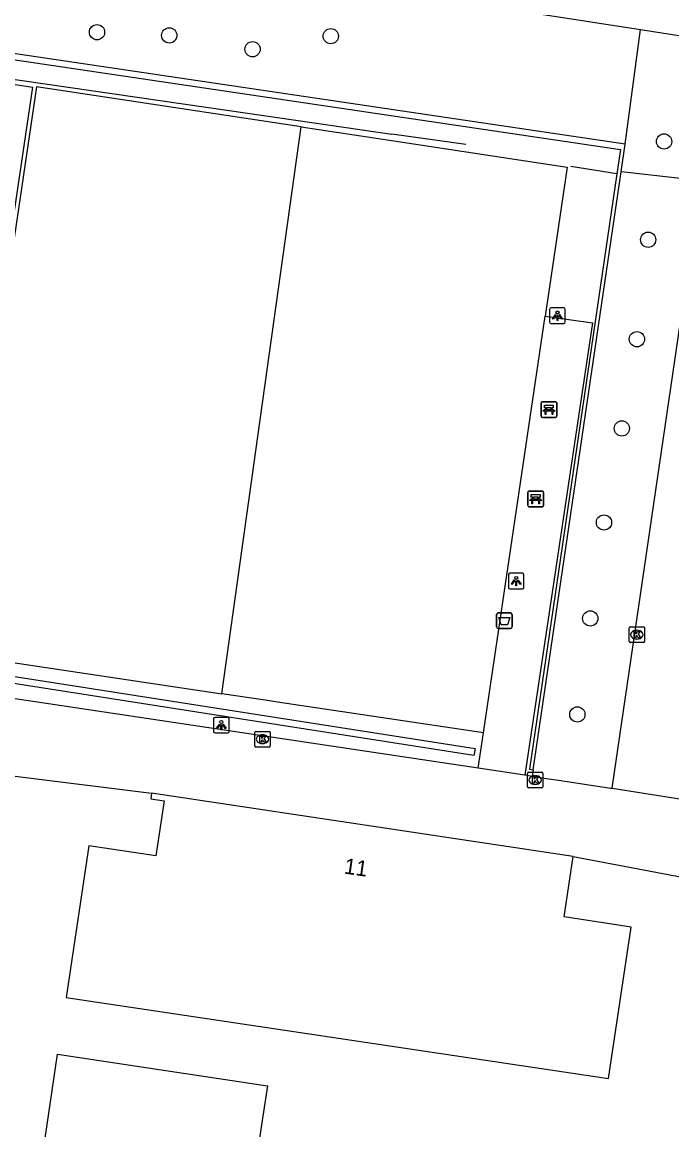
# Model space of a CAD drawing. Extents: x 161094 to 161705, y 379509 to 380907.
# Drawn here: x 161250.2 to 161291.8, y 380398.5 to 380469.4 of the extents above; entities that cross this region are included whole.
import ezdxf

# ---------------------------------------------------------------- set-up
doc = ezdxf.new("R2010")
doc.units = 0
for name, color, linetype in [('IMGEO_Afvalbak', 7, 'Continuous'), ('IMGEO_Bank', 7, 'Continuous'), ('IMGEO_Boom', 7, 'Continuous'), ('IMGEO_Groenvoorziening', 7, 'Continuous'), ('IMGEO_Haag', 7, 'Continuous'), ('IMGEO_Hek', 7, 'Continuous'), ('IMGEO_Kolk', 7, 'Continuous'), ('IMGEO_Lichtpunt', 7, 'Continuous'), ('IMGEO_Pand', 7, 'Continuous'), ('IMGEO_Pand_nummerreeks', 7, 'Continuous'), ('IMGEO_Rijbaan_lokaal_open', 7, 'Continuous'), ('IMGEO_Terreindeel_halfverhard', 7, 'Continuous'), ('IMGEO_Voetpad_gesloten', 7, 'Continuous'), ('IMGEO_Voetpad_open', 7, 'Continuous')]:
    doc.layers.add(name, color=color, linetype=linetype)

msp = doc.modelspace()

# ---------------------------------------------------------------- linework, layer by layer
at = {"layer": 'IMGEO_Afvalbak'}
for p, q in [((161280.569, 380430.712), (161280.569, 380431.512)), ((161280.569, 380431.512), (161280.569, 380430.712)), ((161280.669, 380431.612), (161281.459, 380431.612)), ((161281.459, 380431.612), (161280.669, 380431.612)), ((161281.559, 380431.512), (161281.559, 380430.712)), ((161281.559, 380430.712), (161281.559, 380431.512)), ((161281.459, 380430.612), (161280.669, 380430.612)), ((161280.669, 380430.612), (161281.459, 380430.612))]:
    msp.add_line(p, q, dxfattribs=at)
msp.add_lwpolyline([(161280.712, 380431.326), (161281.416, 380431.326), (161281.267, 380430.856), (161280.861, 380430.856), (161280.712, 380431.326)], dxfattribs=at)
for centre, start, end in [((161280.669, 380431.512), 90, 180), ((161280.669, 380431.512), 90, 180), ((161281.459, 380431.512), 0, 90), ((161281.459, 380431.512), 360, 90), ((161280.669, 380430.712), 180, 270), ((161280.669, 380430.712), 180, 270), ((161281.459, 380430.712), 270, 0), ((161281.459, 380430.712), 270, 0)]:
    msp.add_arc(centre, 0.1, start, end, dxfattribs=at)
at = {"layer": 'IMGEO_Bank'}
for p, q in [((161283.495, 380445.129), (161284.336, 380445.129)), ((161284.336, 380445.129), (161283.495, 380445.129)), ((161283.42, 380444.204), (161283.42, 380445.045)), ((161283.42, 380445.045), (161283.42, 380444.204)), ((161284.117, 380444.527), (161283.724, 380444.527)), ((161283.729, 380444.635), (161283.729, 380444.741)), ((161283.773, 380444.741), (161283.773, 380444.635)), ((161284.061, 380444.747), (161283.779, 380444.747)), ((161283.779, 380444.629), (161284.061, 380444.629)), ((161284.067, 380444.635), (161284.067, 380444.741)), ((161284.111, 380444.741), (161284.111, 380444.635)), ((161284.42, 380445.054), (161284.42, 380444.213)), ((161284.42, 380444.213), (161284.42, 380445.054)), ((161284.345, 380444.129), (161283.504, 380444.129)), ((161283.504, 380444.129), (161284.345, 380444.129)), ((161282.575, 380438.48), (161282.575, 380439.321)), ((161282.575, 380439.321), (161282.575, 380438.48)), ((161282.65, 380439.405), (161283.491, 380439.405)), ((161283.491, 380439.405), (161282.65, 380439.405)), ((161283.272, 380438.803), (161282.879, 380438.803)), ((161282.884, 380438.911), (161282.884, 380439.017)), ((161282.928, 380439.017), (161282.928, 380438.911)), ((161283.216, 380439.023), (161282.934, 380439.023)), ((161282.934, 380438.905), (161283.216, 380438.905)), ((161283.222, 380438.911), (161283.222, 380439.017)), ((161283.266, 380439.017), (161283.266, 380438.911)), ((161283.575, 380439.33), (161283.575, 380438.489)), ((161283.575, 380438.489), (161283.575, 380439.33)), ((161283.5, 380438.405), (161282.659, 380438.405)), ((161282.659, 380438.405), (161283.5, 380438.405))]:
    msp.add_line(p, q, dxfattribs=at)
for points in [[(161283.667, 380444.527), (161283.525, 380444.527), (161283.637, 380444.629), (161283.723, 380444.629)], [(161283.723, 380444.747), (161283.637, 380444.747), (161283.637, 380444.908), (161284.2, 380444.908), (161284.2, 380444.747), (161284.117, 380444.747)], [(161283.717, 380444.52), (161283.717, 380444.313), (161283.674, 380444.313), (161283.674, 380444.52)], [(161284.117, 380444.629), (161284.2, 380444.629), (161284.312, 380444.527), (161284.173, 380444.527)], [(161284.167, 380444.52), (161284.167, 380444.313), (161284.123, 380444.313), (161284.123, 380444.52)], [(161282.822, 380438.803), (161282.68, 380438.803), (161282.792, 380438.905), (161282.878, 380438.905)], [(161282.878, 380439.023), (161282.792, 380439.023), (161282.792, 380439.184), (161283.355, 380439.184), (161283.355, 380439.023), (161283.272, 380439.023)], [(161282.872, 380438.796), (161282.872, 380438.589), (161282.829, 380438.589), (161282.829, 380438.796)], [(161283.272, 380438.905), (161283.355, 380438.905), (161283.467, 380438.803), (161283.328, 380438.803)], [(161283.322, 380438.796), (161283.322, 380438.589), (161283.278, 380438.589), (161283.278, 380438.796)]]:
    msp.add_lwpolyline(points, dxfattribs=at)
for centre, radius, start, end in [((161283.498, 380445.051), 0.0779, 92.4484, 184.28452), ((161283.498, 380445.051), 0.0779, 92.4484, 184.28452), ((161284.342, 380445.051), 0.0779, 2.4484, 94.28452), ((161284.342, 380445.051), 0.0779, 2.4484, 94.28452), ((161283.667, 380444.52), 0.00671, 2.89567, 87.10433), ((161283.724, 380444.52), 0.00671, 92.89567, 177.10433), ((161283.722, 380444.74), 0.00671, 2.89567, 87.10433), ((161283.722, 380444.636), 0.00671, 272.89567, 357.10433), ((161283.779, 380444.74), 0.00671, 92.89567, 177.10433), ((161283.779, 380444.636), 0.00671, 182.89567, 267.10433), ((161284.061, 380444.74), 0.00671, 2.89567, 87.10433), ((161284.061, 380444.636), 0.00671, 272.89567, 357.10433), ((161284.118, 380444.74), 0.00671, 92.89567, 177.10433), ((161284.118, 380444.636), 0.00671, 182.89567, 267.10433), ((161284.116, 380444.52), 0.00671, 2.89567, 87.10433), ((161284.173, 380444.52), 0.00671, 92.89567, 177.10433), ((161283.498, 380444.207), 0.0779, 182.4484, 274.28452), ((161283.498, 380444.207), 0.0779, 182.4484, 274.28452), ((161284.342, 380444.207), 0.0779, 272.4484, 4.28452), ((161284.342, 380444.207), 0.0779, 272.4484, 4.28452), ((161282.653, 380439.327), 0.0779, 92.4484, 184.28452), ((161282.653, 380439.327), 0.0779, 92.4484, 184.28452), ((161282.822, 380438.796), 0.00671, 2.89567, 87.10433), ((161282.879, 380438.796), 0.00671, 92.89567, 177.10433), ((161282.877, 380439.016), 0.00671, 2.89567, 87.10433), ((161282.877, 380438.912), 0.00671, 272.89567, 357.10433), ((161282.934, 380439.016), 0.00671, 92.89567, 177.10433), ((161282.934, 380438.912), 0.00671, 182.89567, 267.10433), ((161283.216, 380439.016), 0.00671, 2.89567, 87.10433), ((161283.216, 380438.912), 0.00671, 272.89567, 357.10433), ((161283.273, 380439.016), 0.00671, 92.89567, 177.10433), ((161283.273, 380438.912), 0.00671, 182.89567, 267.10433), ((161283.271, 380438.796), 0.00671, 2.89567, 87.10433), ((161283.328, 380438.796), 0.00671, 92.89567, 177.10433), ((161283.497, 380439.327), 0.0779, 2.4484, 94.28452), ((161283.497, 380439.327), 0.0779, 2.4484, 94.28452), ((161282.653, 380438.483), 0.0779, 182.4484, 274.28452), ((161282.653, 380438.483), 0.0779, 182.4484, 274.28452), ((161283.497, 380438.483), 0.0779, 272.4484, 4.28452), ((161283.497, 380438.483), 0.0779, 272.4484, 4.28452)]:
    msp.add_arc(centre, radius, start, end, dxfattribs=at)
at = {"layer": 'IMGEO_Boom'}
for centre in [(161254.981, 380468.778), (161259.609, 380468.576), (161269.952, 380468.526), (161264.945, 380467.691), (161291.295, 380461.787), (161290.277, 380455.498), (161289.56, 380449.131), (161288.592, 380443.42), (161287.448, 380437.4), (161286.57, 380431.259), (161285.743, 380425.117)]:
    msp.add_circle(centre, 0.489, dxfattribs=at)
at = {"layer": 'IMGEO_Groenvoorziening'}
for points in [[(161288.807, 380461.604), (161289.794, 380468.952)], [(161268.065, 380462.727), (161251.106, 380465.29), (161245.726, 380429.02), (161262.978, 380426.44)], [(161268.065, 380462.727), (161271.45, 380462.215), (161272.314, 380462.084), (161285.098, 380460.152), (161283.675, 380450.607)], [(161279.724, 380423.935), (161266.543, 380425.906), (161265.906, 380426.002), (161262.978, 380426.44)]]:
    msp.add_lwpolyline(points, dxfattribs=at)
at = {"layer": 'IMGEO_Haag'}
for points in [[(161213.983, 380472.328), (161288.498, 380461.269), (161288.271, 380459.723), (161282.68, 380421.608), (161282.918, 380421.573)], [(161288.807, 380461.604), (161214.037, 380472.701)], [(161288.546, 380459.846), (161288.807, 380461.604)], [(161279.192, 380422.925), (161279.123, 380422.484), (161244.302, 380427.924), (161244.371, 380428.365), (161279.192, 380422.925)]]:
    msp.add_lwpolyline(points, dxfattribs=at)
at = {"layer": 'IMGEO_Hek'}
for points in [[(161213.79, 380470.984), (161267.723, 380463.143)], [(161267.723, 380463.143), (161273.854, 380462.244)], [(161278.602, 380461.594), (161273.854, 380462.244)], [(161288.271, 380459.723), (161285.326, 380460.19)]]:
    msp.add_lwpolyline(points, dxfattribs=at)
at = {"layer": 'IMGEO_Kolk'}
for p, q in [((161289.052, 380429.796), (161289.052, 380430.648)), ((161289.127, 380430.722), (161289.979, 380430.722)), ((161289.54, 380430.502), (161289.565, 380430.502)), ((161290.053, 380430.648), (161290.053, 380429.796)), ((161289.979, 380429.722), (161289.127, 380429.722)), ((161289.563, 380429.942), (161289.538, 380429.942)), ((161265.078, 380423.104), (161265.078, 380423.956)), ((161265.153, 380424.03), (161266.005, 380424.03)), ((161266.079, 380423.956), (161266.079, 380423.104)), ((161265.589, 380423.25), (161265.564, 380423.25)), ((161265.566, 380423.81), (161265.591, 380423.81)), ((161266.005, 380423.03), (161265.153, 380423.03)), ((161282.541, 380420.488), (161282.541, 380421.34)), ((161282.616, 380421.414), (161283.468, 380421.414)), ((161283.029, 380421.194), (161283.054, 380421.194)), ((161283.542, 380421.34), (161283.542, 380420.488)), ((161283.468, 380420.414), (161282.616, 380420.414)), ((161283.052, 380420.634), (161283.027, 380420.634))]:
    msp.add_line(p, q, dxfattribs=at)
for points in [[(161289.052, 380429.796), (161289.052, 380430.648)], [(161289.127, 380430.722), (161289.979, 380430.722)], [(161289.373, 380430.422), (161289.496, 380430.422), (161289.496, 380430.271), (161289.626, 380430.422), (161289.79, 380430.422), (161289.644, 380430.271), (161289.797, 380430.022), (161289.645, 380430.022), (161289.56, 380430.186), (161289.496, 380430.119), (161289.496, 380430.022), (161289.373, 380430.022), (161289.373, 380430.422)], [(161290.053, 380430.648), (161290.053, 380429.796)], [(161289.979, 380429.722), (161289.127, 380429.722)], [(161265.078, 380423.104), (161265.078, 380423.956)], [(161265.153, 380424.03), (161266.005, 380424.03)], [(161266.079, 380423.956), (161266.079, 380423.104)], [(161265.399, 380423.73), (161265.522, 380423.73), (161265.522, 380423.579), (161265.652, 380423.73), (161265.816, 380423.73), (161265.67, 380423.579), (161265.823, 380423.33), (161265.671, 380423.33), (161265.586, 380423.494), (161265.522, 380423.427), (161265.522, 380423.33), (161265.399, 380423.33), (161265.399, 380423.73)], [(161266.005, 380423.03), (161265.153, 380423.03)], [(161282.541, 380420.488), (161282.541, 380421.34)], [(161282.616, 380421.414), (161283.468, 380421.414)], [(161282.862, 380421.114), (161282.985, 380421.114), (161282.985, 380420.963), (161283.115, 380421.114), (161283.279, 380421.114), (161283.133, 380420.963), (161283.286, 380420.714), (161283.134, 380420.714), (161283.049, 380420.878), (161282.985, 380420.811), (161282.985, 380420.714), (161282.862, 380420.714), (161282.862, 380421.114)], [(161283.542, 380421.34), (161283.542, 380420.488)], [(161283.468, 380420.414), (161282.616, 380420.414)]]:
    msp.add_lwpolyline(points, dxfattribs=at)
for centre, start, end in [((161289.129, 380430.646), 91.55205, 178.44795), ((161289.129, 380430.646), 91.55205, 178.44795), ((161289.977, 380430.646), 1.55205, 88.44795), ((161289.977, 380430.646), 1.55205, 88.44795), ((161289.129, 380429.798), 181.55205, 268.44795), ((161289.129, 380429.798), 181.55205, 268.44795), ((161289.977, 380429.798), 271.55205, 358.44795), ((161289.977, 380429.798), 271.55205, 358.44795), ((161265.155, 380423.954), 91.55205, 178.44795), ((161265.155, 380423.954), 91.55205, 178.44795), ((161266.003, 380423.954), 1.55205, 88.44795), ((161266.003, 380423.954), 1.55205, 88.44795), ((161265.155, 380423.106), 181.55205, 268.44795), ((161265.155, 380423.106), 181.55205, 268.44795), ((161266.003, 380423.106), 271.55205, 358.44795), ((161266.003, 380423.106), 271.55205, 358.44795), ((161282.618, 380421.338), 91.55205, 178.44795), ((161282.618, 380421.338), 91.55205, 178.44795), ((161283.466, 380421.338), 1.55205, 88.44795), ((161283.466, 380421.338), 1.55205, 88.44795), ((161282.618, 380420.49), 181.55205, 268.44795), ((161282.618, 380420.49), 181.55205, 268.44795), ((161283.466, 380420.49), 271.55205, 358.44795), ((161283.466, 380420.49), 271.55205, 358.44795)]:
    msp.add_arc(centre, 0.0765, start, end, dxfattribs=at)
for centre, major_axis, ratio, start_param, end_param in [((161289.539, 380430.222), (-0.387, 0.002), 0.722429, 4.712389, 7.853982), ((161289.564, 380430.222), (-0.39, 0.002), 0.717154, 1.570796, 4.712389), ((161265.565, 380423.53), (-0.387, 0.002), 0.722429, 4.712389, 7.853982), ((161265.59, 380423.53), (-0.39, 0.002), 0.717154, 1.570796, 4.712389), ((161283.028, 380420.914), (-0.387, 0.002), 0.722429, 4.712389, 7.853982), ((161283.053, 380420.914), (-0.39, 0.002), 0.717154, 1.570796, 4.712389)]:
    msp.add_ellipse(centre, major_axis=major_axis, ratio=ratio, start_param=start_param, end_param=end_param, dxfattribs=at)
at = {"layer": 'IMGEO_Lichtpunt'}
for p, q in [((161283.969, 380451.04), (161283.969, 380450.233)), ((161283.969, 380451.04), (161283.969, 380450.233)), ((161284.871, 380451.135), (161284.063, 380451.135)), ((161284.871, 380451.135), (161284.063, 380451.135)), ((161284.965, 380450.233), (161284.965, 380451.04)), ((161284.965, 380450.233), (161284.965, 380451.04)), ((161284.063, 380450.139), (161284.871, 380450.139)), ((161284.063, 380450.139), (161284.871, 380450.139)), ((161281.329, 380434.056), (161281.329, 380433.249)), ((161281.329, 380434.056), (161281.329, 380433.249)), ((161282.231, 380434.151), (161281.423, 380434.151)), ((161282.231, 380434.151), (161281.423, 380434.151)), ((161282.325, 380433.249), (161282.325, 380434.056)), ((161282.325, 380433.249), (161282.325, 380434.056)), ((161281.423, 380433.155), (161282.231, 380433.155)), ((161281.423, 380433.155), (161282.231, 380433.155)), ((161262.445, 380424.829), (161262.445, 380424.022)), ((161262.445, 380424.829), (161262.445, 380424.022)), ((161263.347, 380424.924), (161262.539, 380424.924)), ((161263.347, 380424.924), (161262.539, 380424.924)), ((161263.441, 380424.022), (161263.441, 380424.829)), ((161263.441, 380424.022), (161263.441, 380424.829)), ((161262.539, 380423.928), (161263.347, 380423.928)), ((161262.539, 380423.928), (161263.347, 380423.928))]:
    msp.add_line(p, q, dxfattribs=at)
for points in [[(161284.343, 380450.704), (161284.382, 380450.676), (161284.194, 380450.414), (161284.156, 380450.441), (161284.343, 380450.704)], [(161284.445, 380450.656), (161284.492, 380450.656), (161284.492, 380450.334), (161284.445, 380450.334), (161284.445, 380450.656)], [(161284.555, 380450.676), (161284.593, 380450.703), (161284.78, 380450.441), (161284.741, 380450.413), (161284.555, 380450.676)], [(161281.703, 380433.72), (161281.742, 380433.692), (161281.554, 380433.43), (161281.516, 380433.457), (161281.703, 380433.72)], [(161281.805, 380433.672), (161281.852, 380433.672), (161281.852, 380433.35), (161281.805, 380433.35), (161281.805, 380433.672)], [(161281.915, 380433.692), (161281.953, 380433.719), (161282.14, 380433.457), (161282.101, 380433.429), (161281.915, 380433.692)], [(161262.819, 380424.493), (161262.858, 380424.465), (161262.67, 380424.203), (161262.632, 380424.23), (161262.819, 380424.493)], [(161262.921, 380424.445), (161262.968, 380424.445), (161262.968, 380424.123), (161262.921, 380424.123), (161262.921, 380424.445)], [(161263.031, 380424.465), (161263.069, 380424.492), (161263.256, 380424.23), (161263.217, 380424.202), (161263.031, 380424.465)]]:
    msp.add_lwpolyline(points, dxfattribs=at)
for centre in [(161284.468, 380450.838), (161281.828, 380433.854), (161262.944, 380424.627)]:
    msp.add_circle(centre, 0.0994, dxfattribs=at)
for centre, start, end in [((161284.063, 380451.04), 90, 180), ((161284.063, 380451.04), 90, 180), ((161284.871, 380451.04), 0, 90), ((161284.871, 380451.04), 0, 90), ((161284.063, 380450.233), 180, 270), ((161284.063, 380450.233), 180, 270), ((161284.871, 380450.233), 270, 0), ((161284.871, 380450.233), 270, 360), ((161281.423, 380434.056), 90, 180), ((161281.423, 380434.056), 90, 180), ((161282.231, 380434.056), 0, 90), ((161282.231, 380434.056), 0, 90), ((161281.423, 380433.249), 180, 270), ((161281.423, 380433.249), 180, 270), ((161282.231, 380433.249), 270, 0), ((161282.231, 380433.249), 270, 360), ((161262.539, 380424.829), 90, 180), ((161262.539, 380424.829), 90, 180), ((161263.347, 380424.829), 0, 90), ((161263.347, 380424.829), 0, 90), ((161262.539, 380424.022), 180, 270), ((161262.539, 380424.022), 180, 270), ((161263.347, 380424.022), 270, 0), ((161263.347, 380424.022), 270, 360)]:
    msp.add_arc(centre, 0.0946, start, end, dxfattribs=at)
at = {"layer": 'IMGEO_Pand'}
for points in [[(161258.474, 380420.084), (161258.419, 380419.717), (161259.279, 380419.589), (161258.746, 380416.059), (161254.463, 380416.699), (161252.998, 380407.005), (161287.733, 380401.815), (161289.192, 380411.506), (161284.9, 380412.152), (161285.472, 380416.02)], [(161285.472, 380416.02), (161258.474, 380420.084)]]:
    msp.add_lwpolyline(points, dxfattribs=at)
at = {"layer": 'IMGEO_Rijbaan_lokaal_open'}
for points in [[(161287.966, 380420.387), (161293.673, 380459.266)], [(161287.966, 380420.387), (161292.846, 380419.624)]]:
    msp.add_lwpolyline(points, dxfattribs=at)
at = {"layer": 'IMGEO_Terreindeel_halfverhard'}
msp.add_lwpolyline([(161262.978, 380426.44), (161268.065, 380462.727)], dxfattribs=at)
at = {"layer": 'IMGEO_Voetpad_gesloten'}
for points in [[(161218.136, 380480.015), (161289.794, 380468.952)], [(161289.794, 380468.952), (161294.974, 380468.152)]]:
    msp.add_lwpolyline(points, dxfattribs=at)
at = {"layer": 'IMGEO_Voetpad_open'}
for points in [[(161242.91, 380429.37), (161242.819, 380429.374), (161248.213, 380465.672), (161250.851, 380465.255), (161245.479, 380429.036), (161244.277, 380429.158)], [(161282.918, 380421.573), (161288.546, 380459.846)], [(161293.673, 380459.266), (161288.546, 380459.846)], [(161279.724, 380423.935), (161283.675, 380450.607)], [(161283.675, 380450.607), (161286.723, 380450.172), (161282.385, 380421.222)], [(161279.388, 380421.67), (161244.715, 380426.852), (161243.941, 380426.968)], [(161279.388, 380421.67), (161279.724, 380423.935)], [(161241.495, 380422.179), (161258.474, 380420.084)], [(161282.385, 380421.222), (161279.388, 380421.67)], [(161282.856, 380421.152), (161282.385, 380421.222)], [(161282.918, 380421.573), (161282.856, 380421.152)], [(161282.856, 380421.152), (161284.692, 380420.877), (161287.86, 380420.404), (161287.966, 380420.387)], [(161285.472, 380416.02), (161295.711, 380414.078)], [(161264.811, 380394.143), (161263.942, 380388.053), (161250.511, 380390.143), (161252.452, 380403.361), (161265.895, 380401.354), (161265.201, 380396.75)]]:
    msp.add_lwpolyline(points, dxfattribs=at)

# ---------------------------------------------------------------- texts
at = {"layer": 'IMGEO_Pand_nummerreeks'}
msp.add_text('11', height=1, rotation=351.78152, dxfattribs=at).set_placement((161270.762, 380414.938))

doc.saveas('drawing.dxf')
